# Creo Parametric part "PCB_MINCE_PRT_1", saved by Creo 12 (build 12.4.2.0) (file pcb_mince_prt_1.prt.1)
Units: Custom; MM, KILOGRAM, SECS

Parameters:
  PTC_WM_ITERATION = "0"
  PTC_WM_VERSION = "-.0"
  PTC_WM_LIFECYCLE_STATE = "In Work"
  PTC_WM_LIFECYCLE = "MO_CADDocument"
  PTC_WM_CREATED_BY = "Maximilian Roepper (Z0017RMS: MO)"
  PTC_WM_CREATED_ON = "18-Sep-26 11:36:42 AM"
  PTC_WM_MODIFIED_BY = "Maximilian Roepper (Z0017RMS: MO)"
  PTC_WM_MODIFIED_ON = "18-Sep-26 11:36:46 AM"
  PDMLINKNUMBER = "PDM000071455171"
  PTC_WM_NAME = "pcb_mince_prt_1.prt"
  PTC_WM_NUMBER = "PDM000071455171"

Other parameters: WEIGHT, WEIGHT_FACTOR, WEIGHT_ADD, _MASS_TEMP, _DIFF_TEMP, MC_ERRORS, SUPPLIER

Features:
  1. coordinate system
  2. datum plane "PRT_YZ"
  3. datum plane "PRT_XY"
  4. datum plane "PRT_XZ"
  5. coordinate system
  6. datum axis
  7. datum axis
  8. datum axis
  9. coordinate system
  10. imported feature
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
Other named items: PRT, SIEMENS_MO, DRW_VIEW_ORG, PRT_X, PRT_Y, PRT_Z, CS0, ROUGH_GROB

Layers: 00_STD_CSYS-KSYS, 01_STD_PLANES-EBENEN, 02_STD_AXES-ACHSEN, 03_STD_CSYS-KSYS, 24_IMPORT_FEAT-IMPORT_KE

Surfaces: 73 plane, 38 cylinder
